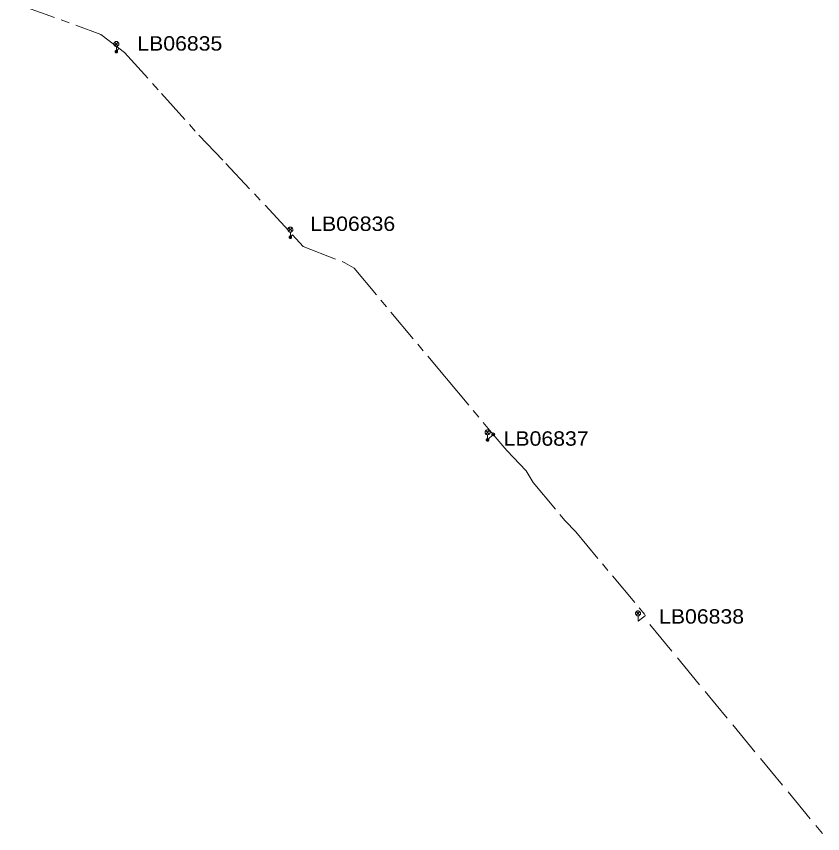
# Model space of a CAD drawing. Extents: x -686371 to -686009, y -974088 to -973838.
# Drawn here: x -686134.5 to -686013.3, y -974088.2 to -973965.5 of the extents above; entities that cross this region are included whole.
import ezdxf

# ---------------------------------------------------------------- set-up
doc = ezdxf.new("R2010")
doc.units = 0
doc.header["$LTSCALE"] = 0.87
doc.header["$PDMODE"] = 32
doc.header["$PDSIZE"] = 0.435
doc.linetypes.add('LONG_DASH_SHORT_DASH', pattern=[9.9, 6, -1.2, 1.5, -1.2])
doc.linetypes.add('LONG_DASHED', pattern=[7.5, 6, -1.5])
doc.layers.add('1', color=7, linetype='Continuous', lineweight=13)

msp = doc.modelspace()

# ---------------------------------------------------------------- linework, layer by layer
at = {"layer": '1', "linetype": 'LONG_DASH_SHORT_DASH'}
for p, q in [((-686121.76, -973968.2), (-686119.06, -973970.24)), ((-686119.44, -973970.78), (-686119.06, -973970.24)), ((-686102.99, -973987.57), (-686092.98, -973998.3)), ((-686093.3, -973998.66), (-686092.98, -973998.3)), ((-686063.68, -974029.11), (-686062.82, -974028.28)), ((-686039.94, -974055.47), (-686041.07, -974056.31))]:
    msp.add_line(p, q, dxfattribs=at)
at = {"layer": '1'}
for p, q in [((-686119.705, -973969.365), (-686119.175, -973969.895)), ((-686119.705, -973969.895), (-686119.175, -973969.365)), ((-686119.44, -973970.78), (-686119.44, -973970.005)), ((-686093.565, -973997.245), (-686093.035, -973997.775)), ((-686093.565, -973997.775), (-686093.035, -973997.245)), ((-686093.3, -973998.66), (-686093.3, -973997.885)), ((-686063.945, -974027.695), (-686063.415, -974028.225)), ((-686063.945, -974028.225), (-686063.415, -974027.695)), ((-686063.68, -974029.11), (-686063.68, -974028.335)), ((-686041.335, -974054.895), (-686040.805, -974055.425)), ((-686041.335, -974055.425), (-686040.805, -974054.895)), ((-686041.07, -974056.31), (-686041.07, -974055.535))]:
    msp.add_line(p, q, dxfattribs=at)
at = {"layer": '1', "linetype": 'LONG_DASHED'}
msp.add_line((-686039.3, -974056.82), (-686013.34, -974088.25), dxfattribs=at)
at = {"layer": '1', "linetype": 'LONG_DASH_SHORT_DASH'}
for points in [[(-686134.47, -973962.76), (-686133.63, -973963.89), (-686121.76, -973968.2)], [(-686119.06, -973970.24), (-686118.2, -973970.89), (-686112.65, -973977.08), (-686107.04, -973983.32), (-686102.99, -973987.57)], [(-686092.98, -973998.3), (-686091.36, -974000.04), (-686085.1, -974002.5), (-686083.72, -974003.33)], [(-686083.72, -974003.33), (-686069.87, -974019.9), (-686062.82, -974028.28)], [(-686062.82, -974028.28), (-686060.79, -974030.7), (-686057.88, -974033.75), (-686056.83, -974035.5), (-686052.03, -974041.27), (-686050.44, -974042.89), (-686039.94, -974055.47)]]:
    msp.add_lwpolyline(points, dxfattribs=at)
at = {"layer": '1'}
for points in [[(-686119.065, -973969.63), (-686119.071, -973969.565), (-686119.088, -973969.502), (-686119.115, -973969.442), (-686119.153, -973969.389), (-686119.199, -973969.343), (-686119.253, -973969.305), (-686119.312, -973969.278), (-686119.375, -973969.261), (-686119.44, -973969.255), (-686119.505, -973969.261), (-686119.568, -973969.278), (-686119.628, -973969.305), (-686119.681, -973969.343), (-686119.727, -973969.389), (-686119.765, -973969.442), (-686119.792, -973969.502), (-686119.809, -973969.565), (-686119.815, -973969.63), (-686119.809, -973969.695), (-686119.792, -973969.758), (-686119.765, -973969.818), (-686119.727, -973969.871), (-686119.681, -973969.917), (-686119.628, -973969.955), (-686119.568, -973969.982), (-686119.505, -973969.999), (-686119.44, -973970.005), (-686119.375, -973969.999), (-686119.312, -973969.982), (-686119.253, -973969.955), (-686119.199, -973969.917), (-686119.153, -973969.871), (-686119.115, -973969.818), (-686119.088, -973969.758), (-686119.071, -973969.695)], [(-686119.25, -973970.78), (-686119.253, -973970.747), (-686119.261, -973970.715), (-686119.275, -973970.685), (-686119.294, -973970.658), (-686119.318, -973970.634), (-686119.345, -973970.615), (-686119.375, -973970.601), (-686119.407, -973970.593), (-686119.44, -973970.59), (-686119.473, -973970.593), (-686119.505, -973970.601), (-686119.535, -973970.615), (-686119.562, -973970.634), (-686119.586, -973970.658), (-686119.605, -973970.685), (-686119.619, -973970.715), (-686119.627, -973970.747), (-686119.63, -973970.78), (-686119.627, -973970.813), (-686119.619, -973970.845), (-686119.605, -973970.875), (-686119.586, -973970.902), (-686119.562, -973970.926), (-686119.535, -973970.945), (-686119.505, -973970.959), (-686119.473, -973970.967), (-686119.44, -973970.97), (-686119.407, -973970.967), (-686119.375, -973970.959), (-686119.345, -973970.945), (-686119.318, -973970.926), (-686119.294, -973970.902), (-686119.275, -973970.875), (-686119.261, -973970.845), (-686119.253, -973970.813)], [(-686119.39, -973970.78), (-686119.391, -973970.771), (-686119.393, -973970.763), (-686119.397, -973970.755), (-686119.402, -973970.748), (-686119.408, -973970.742), (-686119.415, -973970.737), (-686119.423, -973970.733), (-686119.431, -973970.731), (-686119.44, -973970.73), (-686119.449, -973970.731), (-686119.457, -973970.733), (-686119.465, -973970.737), (-686119.472, -973970.742), (-686119.478, -973970.748), (-686119.483, -973970.755), (-686119.487, -973970.763), (-686119.489, -973970.771), (-686119.49, -973970.78), (-686119.489, -973970.789), (-686119.487, -973970.797), (-686119.483, -973970.805), (-686119.478, -973970.812), (-686119.472, -973970.818), (-686119.465, -973970.823), (-686119.457, -973970.827), (-686119.449, -973970.829), (-686119.44, -973970.83), (-686119.431, -973970.829), (-686119.423, -973970.827), (-686119.415, -973970.823), (-686119.408, -973970.818), (-686119.402, -973970.812), (-686119.397, -973970.805), (-686119.393, -973970.797), (-686119.391, -973970.789)], [(-686092.925, -973997.51), (-686092.931, -973997.445), (-686092.948, -973997.382), (-686092.975, -973997.322), (-686093.013, -973997.269), (-686093.059, -973997.223), (-686093.112, -973997.185), (-686093.172, -973997.158), (-686093.235, -973997.141), (-686093.3, -973997.135), (-686093.365, -973997.141), (-686093.428, -973997.158), (-686093.488, -973997.185), (-686093.541, -973997.223), (-686093.587, -973997.269), (-686093.625, -973997.322), (-686093.652, -973997.382), (-686093.669, -973997.445), (-686093.675, -973997.51), (-686093.669, -973997.575), (-686093.652, -973997.638), (-686093.625, -973997.698), (-686093.587, -973997.751), (-686093.541, -973997.797), (-686093.488, -973997.835), (-686093.428, -973997.862), (-686093.365, -973997.879), (-686093.3, -973997.885), (-686093.235, -973997.879), (-686093.172, -973997.862), (-686093.112, -973997.835), (-686093.059, -973997.797), (-686093.013, -973997.751), (-686092.975, -973997.698), (-686092.948, -973997.638), (-686092.931, -973997.575)], [(-686093.11, -973998.66), (-686093.113, -973998.627), (-686093.121, -973998.595), (-686093.135, -973998.565), (-686093.154, -973998.538), (-686093.178, -973998.514), (-686093.205, -973998.495), (-686093.235, -973998.481), (-686093.267, -973998.473), (-686093.3, -973998.47), (-686093.333, -973998.473), (-686093.365, -973998.481), (-686093.395, -973998.495), (-686093.422, -973998.514), (-686093.446, -973998.538), (-686093.465, -973998.565), (-686093.479, -973998.595), (-686093.487, -973998.627), (-686093.49, -973998.66), (-686093.487, -973998.693), (-686093.479, -973998.725), (-686093.465, -973998.755), (-686093.446, -973998.782), (-686093.422, -973998.806), (-686093.395, -973998.825), (-686093.365, -973998.839), (-686093.333, -973998.847), (-686093.3, -973998.85), (-686093.267, -973998.847), (-686093.235, -973998.839), (-686093.205, -973998.825), (-686093.178, -973998.806), (-686093.154, -973998.782), (-686093.135, -973998.755), (-686093.121, -973998.725), (-686093.113, -973998.693)], [(-686093.25, -973998.66), (-686093.251, -973998.651), (-686093.253, -973998.643), (-686093.257, -973998.635), (-686093.262, -973998.628), (-686093.268, -973998.622), (-686093.275, -973998.617), (-686093.283, -973998.613), (-686093.291, -973998.611), (-686093.3, -973998.61), (-686093.309, -973998.611), (-686093.317, -973998.613), (-686093.325, -973998.617), (-686093.332, -973998.622), (-686093.338, -973998.628), (-686093.343, -973998.635), (-686093.347, -973998.643), (-686093.349, -973998.651), (-686093.35, -973998.66), (-686093.349, -973998.669), (-686093.347, -973998.677), (-686093.343, -973998.685), (-686093.338, -973998.692), (-686093.332, -973998.698), (-686093.325, -973998.703), (-686093.317, -973998.707), (-686093.309, -973998.709), (-686093.3, -973998.71), (-686093.291, -973998.709), (-686093.283, -973998.707), (-686093.275, -973998.703), (-686093.268, -973998.698), (-686093.262, -973998.692), (-686093.257, -973998.685), (-686093.253, -973998.677), (-686093.251, -973998.669)], [(-686063.305, -974027.96), (-686063.311, -974027.895), (-686063.328, -974027.832), (-686063.355, -974027.772), (-686063.393, -974027.719), (-686063.439, -974027.673), (-686063.492, -974027.635), (-686063.552, -974027.608), (-686063.615, -974027.591), (-686063.68, -974027.585), (-686063.745, -974027.591), (-686063.808, -974027.608), (-686063.868, -974027.635), (-686063.921, -974027.673), (-686063.967, -974027.719), (-686064.005, -974027.772), (-686064.032, -974027.832), (-686064.049, -974027.895), (-686064.055, -974027.96), (-686064.049, -974028.025), (-686064.032, -974028.088), (-686064.005, -974028.148), (-686063.967, -974028.201), (-686063.921, -974028.247), (-686063.868, -974028.285), (-686063.808, -974028.312), (-686063.745, -974028.329), (-686063.68, -974028.335), (-686063.615, -974028.329), (-686063.552, -974028.312), (-686063.492, -974028.285), (-686063.439, -974028.247), (-686063.393, -974028.201), (-686063.355, -974028.148), (-686063.328, -974028.088), (-686063.311, -974028.025)], [(-686063.49, -974029.11), (-686063.493, -974029.077), (-686063.501, -974029.045), (-686063.515, -974029.015), (-686063.534, -974028.988), (-686063.558, -974028.964), (-686063.585, -974028.945), (-686063.615, -974028.931), (-686063.647, -974028.923), (-686063.68, -974028.92), (-686063.713, -974028.923), (-686063.745, -974028.931), (-686063.775, -974028.945), (-686063.802, -974028.964), (-686063.826, -974028.988), (-686063.845, -974029.015), (-686063.859, -974029.045), (-686063.867, -974029.077), (-686063.87, -974029.11), (-686063.867, -974029.143), (-686063.859, -974029.175), (-686063.845, -974029.205), (-686063.826, -974029.232), (-686063.802, -974029.256), (-686063.775, -974029.275), (-686063.745, -974029.289), (-686063.713, -974029.297), (-686063.68, -974029.3), (-686063.647, -974029.297), (-686063.615, -974029.289), (-686063.585, -974029.275), (-686063.558, -974029.256), (-686063.534, -974029.232), (-686063.515, -974029.205), (-686063.501, -974029.175), (-686063.493, -974029.143)], [(-686063.63, -974029.11), (-686063.631, -974029.101), (-686063.633, -974029.093), (-686063.637, -974029.085), (-686063.642, -974029.078), (-686063.648, -974029.072), (-686063.655, -974029.067), (-686063.663, -974029.063), (-686063.671, -974029.061), (-686063.68, -974029.06), (-686063.689, -974029.061), (-686063.697, -974029.063), (-686063.705, -974029.067), (-686063.712, -974029.072), (-686063.718, -974029.078), (-686063.723, -974029.085), (-686063.727, -974029.093), (-686063.729, -974029.101), (-686063.73, -974029.11), (-686063.729, -974029.119), (-686063.727, -974029.127), (-686063.723, -974029.135), (-686063.718, -974029.142), (-686063.712, -974029.148), (-686063.705, -974029.153), (-686063.697, -974029.157), (-686063.689, -974029.159), (-686063.68, -974029.16), (-686063.671, -974029.159), (-686063.663, -974029.157), (-686063.655, -974029.153), (-686063.648, -974029.148), (-686063.642, -974029.142), (-686063.637, -974029.135), (-686063.633, -974029.127), (-686063.631, -974029.119)], [(-686040.695, -974055.16), (-686040.701, -974055.095), (-686040.718, -974055.032), (-686040.745, -974054.972), (-686040.783, -974054.919), (-686040.829, -974054.873), (-686040.883, -974054.835), (-686040.942, -974054.808), (-686041.005, -974054.791), (-686041.07, -974054.785), (-686041.135, -974054.791), (-686041.198, -974054.808), (-686041.258, -974054.835), (-686041.311, -974054.873), (-686041.357, -974054.919), (-686041.395, -974054.972), (-686041.422, -974055.032), (-686041.439, -974055.095), (-686041.445, -974055.16), (-686041.439, -974055.225), (-686041.422, -974055.288), (-686041.395, -974055.348), (-686041.357, -974055.401), (-686041.311, -974055.447), (-686041.258, -974055.485), (-686041.198, -974055.512), (-686041.135, -974055.529), (-686041.07, -974055.535), (-686041.005, -974055.529), (-686040.942, -974055.512), (-686040.883, -974055.485), (-686040.829, -974055.447), (-686040.783, -974055.401), (-686040.745, -974055.348), (-686040.718, -974055.288), (-686040.701, -974055.225)]]:
    msp.add_lwpolyline(points, close=True, dxfattribs=at)
msp.add_point((-686062.82, -974028.28), dxfattribs=at)

# ---------------------------------------------------------------- texts
at = {"layer": '1', "width": 1.1}
for s, p in [('LB06835', (-686116.295, -973970.631)), ('LB06836', (-686090.324, -973997.719)), ('LB06837', (-686061.265, -974029.978)), ('LB06838', (-686037.914, -974056.704))]:
    msp.add_text(s, height=2.167, dxfattribs=at).set_placement(p)

doc.saveas('drawing.dxf')
